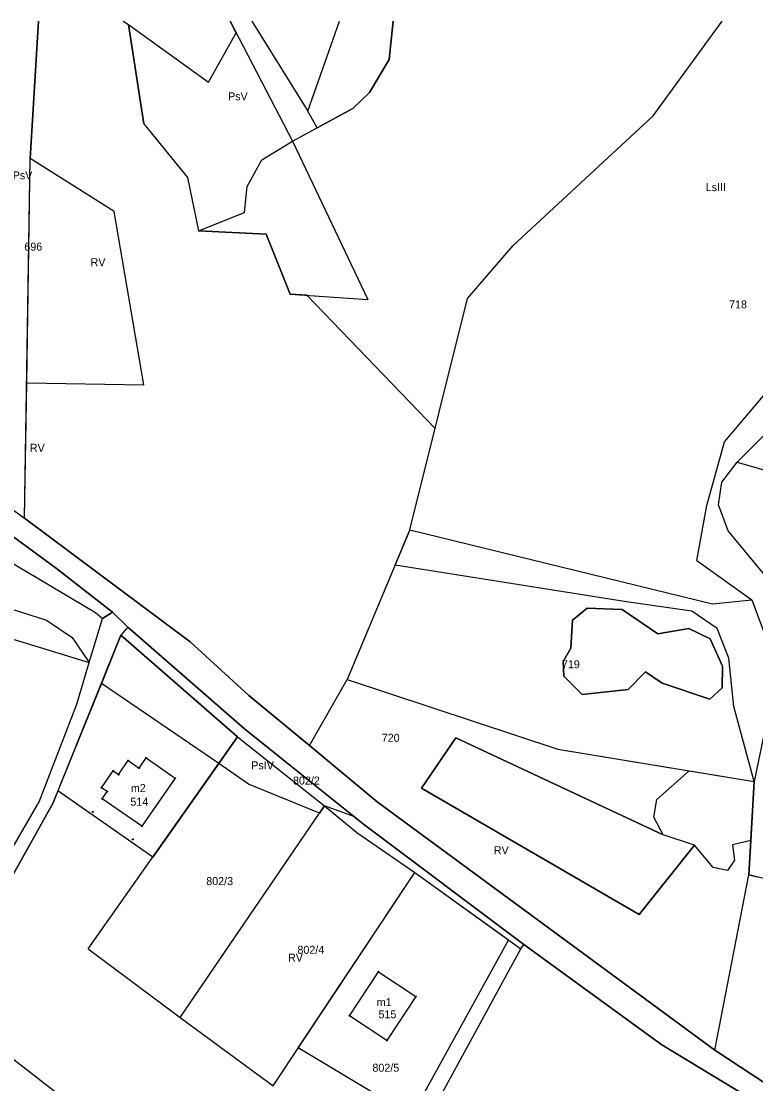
# Model space of a CAD drawing. Extents: x 7498273 to 7499989, y 5499795 to 5500810.
# Drawn here: x 7499690.9 to 7499828.5, y 5500610.4 to 5500809.6 of the extents above; entities that cross this region are included whole.
import ezdxf

# ---------------------------------------------------------------- set-up
doc = ezdxf.new("R2010")
doc.units = 0
for name, color, linetype in [('209-oznaczenie konturu klasyfikacyjnego', 7, 'Continuous'), ('211-numer działki ewidencyjnej', 7, 'Continuous'), ('217-kontur klasyfikacyjny', 7, 'Continuous'), ('218-kontur użytku gruntowego', 7, 'Continuous'), ('219-działka ewidencyjna', 7, 'Continuous'), ('312-budynek ewidencyjny', 7, 'Continuous'), ('312-oznaczenie budynku ewidencyjnego', 7, 'Continuous'), ('312-oznaczenie budynku ewidencyjnego-Atr117', 7, 'Continuous'), ('Punkt budynku', 7, 'Continuous')]:
    doc.layers.add(name, color=color, linetype=linetype)

# ---------------------------------------------------------------- blocks, each defined once
blk = doc.blocks.new('PUNKTBUD')
blk.add_circle((0, 0), 0.09)

msp = doc.modelspace()

# ---------------------------------------------------------------- linework, layer by layer
at = {"layer": '217-kontur klasyfikacyjny'}
for points in [[(7499692.6, 5500783.85), (7499694.121, 5500809.555)], [(7499710.006, 5500809.555), (7499711, 5500808.93)], [(7499731.16, 5500807.4), (7499730.036, 5500809.555)], [(7499734.114, 5500809.555), (7499744.63, 5500792.71)], [(7499744.63, 5500792.71), (7499750.533, 5500809.555)], [(7499760.6, 5500809.555), (7499759.83, 5500802.4)], [(7499711, 5500808.93), (7499725.99, 5500798.12)], [(7499711, 5500808.93), (7499713.85, 5500790.36)], [(7499725.99, 5500798.12), (7499731.16, 5500807.4)], [(7499759.83, 5500802.4), (7499756.17, 5500796.19)], [(7499756.17, 5500796.19), (7499753.05, 5500793.18)], [(7499753.05, 5500793.18), (7499746.33, 5500789.55)], [(7499746.33, 5500789.55), (7499744.63, 5500792.71)], [(7499713.85, 5500790.36), (7499722.07, 5500780.25)], [(7499741.76, 5500787.08), (7499746.33, 5500789.55)], [(7499736, 5500783.58), (7499741.76, 5500787.08)], [(7499691.93, 5500741.79), (7499692.6, 5500783.85)], [(7499708.34, 5500773.87), (7499692.6, 5500783.85)], [(7499733.24, 5500778.61), (7499736, 5500783.58)], [(7499722.07, 5500780.25), (7499724.13, 5500770.26)], [(7499732.76, 5500773.71), (7499733.24, 5500778.61)], [(7499713.89, 5500741.44), (7499708.34, 5500773.87)], [(7499724.13, 5500770.26), (7499732.76, 5500773.71)], [(7499736.78, 5500769.67), (7499724.13, 5500770.26)], [(7499741.31, 5500758.42), (7499736.78, 5500769.67)], [(7499744.4, 5500758.21), (7499741.31, 5500758.42)], [(7499768.47, 5500733.21), (7499744.4, 5500758.21)], [(7499691.53, 5500716.43), (7499691.93, 5500741.79)], [(7499691.93, 5500741.79), (7499713.89, 5500741.44)], [(7499831.76, 5500733.58), (7499825.08, 5500726.95)], [(7499763.74, 5500714.23), (7499768.47, 5500733.21)], [(7499822.18, 5500723.15), (7499825.08, 5500726.95)], [(7499825.08, 5500726.95), (7499880.65, 5500710.94)], [(7499821.56, 5500718.94), (7499822.18, 5500723.15)], [(7499697.51, 5500706.97), (7499681.88, 5500718.4)], [(7499688.31, 5500718.73), (7499691.53, 5500716.43)], [(7499823.35, 5500714.05), (7499821.56, 5500718.94)], [(7499691.53, 5500716.43), (7499722.55, 5500693.26)], [(7499761, 5500707.59), (7499763.74, 5500714.23)], [(7499831.16, 5500704.65), (7499823.35, 5500714.05)], [(7499804.34, 5500700.75), (7499761, 5500707.59)], [(7499708, 5500698.79), (7499697.51, 5500706.97)], [(7499683.07, 5500701.33), (7499695.62, 5500697.33)], [(7499816.55, 5500699.03), (7499804.34, 5500700.75)], [(7499703.63, 5500689.35), (7499706.14, 5500697.61)], [(7499706.14, 5500697.61), (7499708, 5500698.79)], [(7499794.18, 5500697.3), (7499796.97, 5500699.58)], [(7499796.97, 5500699.58), (7499803.48, 5500699.32)], [(7499803.48, 5500699.32), (7499810.16, 5500694.75)], [(7499821.31, 5500695.78), (7499816.55, 5500699.03)], [(7499695.62, 5500697.33), (7499700.45, 5500694.09)], [(7499710.9, 5500695.99), (7499709.58, 5500694.48)], [(7499732.77, 5500676.94), (7499710.9, 5500695.99)], [(7499793.87, 5500692.04), (7499794.18, 5500697.3)], [(7499810.16, 5500694.75), (7499815.98, 5500695.74)], [(7499815.98, 5500695.74), (7499819.99, 5500693.84)], [(7499823.52, 5500690.2), (7499821.31, 5500695.78)], [(7499700.45, 5500694.09), (7499703.63, 5500689.35)], [(7499709.58, 5500694.48), (7499705.92, 5500685.43)], [(7499819.99, 5500693.84), (7499822.28, 5500688.71)], [(7499722.55, 5500693.26), (7499733.56, 5500683.18)], [(7499792.45, 5500689.54), (7499793.87, 5500692.04)], [(7499824.44, 5500681.15), (7499823.52, 5500690.2)], [(7499701.31, 5500681.59), (7499703.63, 5500689.35)], [(7499792.58, 5500686.79), (7499792.45, 5500689.54)], [(7499822.28, 5500688.71), (7499822.22, 5500684.61)], [(7499744.93, 5500673.82), (7499751.95, 5500686.19)], [(7499751.95, 5500686.19), (7499791.46, 5500673.13)], [(7499796.03, 5500683.41), (7499792.58, 5500686.79)], [(7499807.88, 5500687.62), (7499804.62, 5500684.31)], [(7499810.98, 5500685.52), (7499807.88, 5500687.62)], [(7499705.92, 5500685.43), (7499697.79, 5500665.31)], [(7499727.91, 5500670.43), (7499705.92, 5500685.43)], [(7499804.62, 5500684.31), (7499796.03, 5500683.41)], [(7499819.93, 5500682.48), (7499810.98, 5500685.52)], [(7499822.22, 5500684.61), (7499819.93, 5500682.48)], [(7499733.56, 5500683.18), (7499744.93, 5500673.82)], [(7499694.3, 5500663.26), (7499701.31, 5500681.59)], [(7499828.25, 5500667.1), (7499824.44, 5500681.15)], [(7499753.2, 5500660.55), (7499732.77, 5500676.94)], [(7499744.93, 5500673.82), (7499757.58, 5500663.24)], [(7499765.9, 5500665.82), (7499772.34, 5500675.25)], [(7499772.34, 5500675.25), (7499811.21, 5500657.07)], [(7499791.46, 5500673.13), (7499816.06, 5500669.1)], [(7499733.52, 5500666.58), (7499727.91, 5500670.43)], [(7499810.02, 5500663.71), (7499816.06, 5500669.1)], [(7499816.06, 5500669.1), (7499828.25, 5500667.1)], [(7499746.78, 5500661.13), (7499733.52, 5500666.58)], [(7499806.72, 5500642.18), (7499765.9, 5500665.82)], [(7499828.25, 5500667.1), (7499827.59, 5500656)], [(7499697.79, 5500665.31), (7499696.89, 5500663.08)], [(7499681.96, 5500642.08), (7499694.3, 5500663.26)], [(7499696.89, 5500663.08), (7499684.81, 5500641.58)], [(7499747.73, 5500662.52), (7499746.78, 5500661.13)], [(7499753.2, 5500660.55), (7499747.73, 5500662.52)], [(7499757.58, 5500663.24), (7499820.89, 5500616.74)], [(7499809.45, 5500660.39), (7499810.02, 5500663.71)], [(7499755.04, 5500659.07), (7499753.2, 5500660.55)], [(7499811.21, 5500657.07), (7499809.45, 5500660.39)], [(7499785.09, 5500636.56), (7499755.04, 5500659.07)], [(7499827.59, 5500656), (7499824.15, 5500655.21)], [(7499827.59, 5500656), (7499827.21, 5500649.6)], [(7499817.08, 5500655.13), (7499806.72, 5500642.18)], [(7499820.53, 5500650.95), (7499817.08, 5500655.13)], [(7499824.15, 5500655.21), (7499824.58, 5500652.32)], [(7499824.58, 5500652.32), (7499823.24, 5500650.38)], [(7499742.82, 5500617.18), (7499764.64, 5500650.03)], [(7499764.64, 5500650.03), (7499782.19, 5500637.42)], [(7499823.24, 5500650.38), (7499820.53, 5500650.95)], [(7499820.89, 5500616.74), (7499827.21, 5500649.6)], [(7499827.21, 5500649.6), (7499828.82, 5500649.2)], [(7499782.19, 5500637.42), (7499764.06, 5500604.45)], [(7499810.94, 5500617.72), (7499785.09, 5500636.56)], [(7499747.57, 5500569.82), (7499677.4, 5500624.27)], [(7499764.06, 5500604.45), (7499742.82, 5500617.18)], [(7499834.34, 5500603.52), (7499810.94, 5500617.72)], [(7499820.89, 5500616.74), (7499830.36, 5500610.47)]]:
    msp.add_lwpolyline(points, dxfattribs=at)
at = {"layer": '218-kontur użytku gruntowego'}
for points in [[(7499692.6, 5500783.85), (7499694.121, 5500809.555)], [(7499710.006, 5500809.555), (7499711, 5500808.93)], [(7499731.16, 5500807.4), (7499730.036, 5500809.555)], [(7499734.114, 5500809.555), (7499744.63, 5500792.71)], [(7499744.63, 5500792.71), (7499750.533, 5500809.555)], [(7499759.83, 5500802.4), (7499760.6, 5500809.555)], [(7499711, 5500808.93), (7499725.99, 5500798.12)], [(7499711, 5500808.93), (7499713.85, 5500790.36)], [(7499725.99, 5500798.12), (7499731.16, 5500807.4)], [(7499756.17, 5500796.19), (7499759.83, 5500802.4)], [(7499753.05, 5500793.18), (7499756.17, 5500796.19)], [(7499746.33, 5500789.55), (7499753.05, 5500793.18)], [(7499746.33, 5500789.55), (7499744.63, 5500792.71)], [(7499713.85, 5500790.36), (7499722.07, 5500780.25)], [(7499741.76, 5500787.08), (7499746.33, 5500789.55)], [(7499736, 5500783.58), (7499741.76, 5500787.08)], [(7499691.93, 5500741.79), (7499692.6, 5500783.85)], [(7499708.34, 5500773.87), (7499692.6, 5500783.85)], [(7499733.24, 5500778.61), (7499736, 5500783.58)], [(7499722.07, 5500780.25), (7499724.13, 5500770.26)], [(7499732.76, 5500773.71), (7499733.24, 5500778.61)], [(7499713.89, 5500741.44), (7499708.34, 5500773.87)], [(7499724.13, 5500770.26), (7499732.76, 5500773.71)], [(7499736.78, 5500769.67), (7499724.13, 5500770.26)], [(7499741.31, 5500758.42), (7499736.78, 5500769.67)], [(7499744.4, 5500758.21), (7499741.31, 5500758.42)], [(7499768.47, 5500733.21), (7499744.4, 5500758.21)], [(7499691.53, 5500716.43), (7499691.93, 5500741.79)], [(7499691.93, 5500741.79), (7499713.89, 5500741.44)], [(7499831.76, 5500733.58), (7499825.08, 5500726.95)], [(7499763.74, 5500714.23), (7499768.47, 5500733.21)], [(7499822.18, 5500723.15), (7499825.08, 5500726.95)], [(7499825.08, 5500726.95), (7499880.65, 5500710.94)], [(7499821.56, 5500718.94), (7499822.18, 5500723.15)], [(7499697.51, 5500706.97), (7499681.88, 5500718.4)], [(7499688.31, 5500718.73), (7499691.53, 5500716.43)], [(7499823.35, 5500714.05), (7499821.56, 5500718.94)], [(7499722.55, 5500693.26), (7499691.53, 5500716.43)], [(7499761, 5500707.59), (7499763.74, 5500714.23)], [(7499831.16, 5500704.65), (7499823.35, 5500714.05)], [(7499804.34, 5500700.75), (7499761, 5500707.59)], [(7499708, 5500698.79), (7499697.51, 5500706.97)], [(7499683.07, 5500701.33), (7499695.62, 5500697.33)], [(7499816.55, 5500699.03), (7499804.34, 5500700.75)], [(7499703.63, 5500689.35), (7499706.14, 5500697.61)], [(7499706.14, 5500697.61), (7499708, 5500698.79)], [(7499796.97, 5500699.58), (7499794.18, 5500697.3)], [(7499803.48, 5500699.32), (7499796.97, 5500699.58)], [(7499810.16, 5500694.75), (7499803.48, 5500699.32)], [(7499821.31, 5500695.78), (7499816.55, 5500699.03)], [(7499695.62, 5500697.33), (7499700.45, 5500694.09)], [(7499710.9, 5500695.99), (7499709.58, 5500694.48)], [(7499732.77, 5500676.94), (7499710.9, 5500695.99)], [(7499794.18, 5500697.3), (7499793.87, 5500692.04)], [(7499815.98, 5500695.74), (7499810.16, 5500694.75)], [(7499819.99, 5500693.84), (7499815.98, 5500695.74)], [(7499823.52, 5500690.2), (7499821.31, 5500695.78)], [(7499700.45, 5500694.09), (7499703.63, 5500689.35)], [(7499709.58, 5500694.48), (7499705.92, 5500685.43)], [(7499709.58, 5500694.48), (7499731.44, 5500675.44)], [(7499822.28, 5500688.71), (7499819.99, 5500693.84)], [(7499733.56, 5500683.18), (7499722.55, 5500693.26)], [(7499793.87, 5500692.04), (7499792.45, 5500689.54)], [(7499824.44, 5500681.15), (7499823.52, 5500690.2)], [(7499701.31, 5500681.59), (7499703.63, 5500689.35)], [(7499792.45, 5500689.54), (7499792.58, 5500686.79)], [(7499822.22, 5500684.61), (7499822.28, 5500688.71)], [(7499744.93, 5500673.82), (7499751.95, 5500686.19)], [(7499751.95, 5500686.19), (7499791.46, 5500673.13)], [(7499792.58, 5500686.79), (7499796.03, 5500683.41)], [(7499804.62, 5500684.31), (7499807.88, 5500687.62)], [(7499807.88, 5500687.62), (7499810.98, 5500685.52)], [(7499705.92, 5500685.43), (7499697.79, 5500665.31)], [(7499727.91, 5500670.43), (7499705.92, 5500685.43)], [(7499796.03, 5500683.41), (7499804.62, 5500684.31)], [(7499810.98, 5500685.52), (7499819.93, 5500682.48)], [(7499819.93, 5500682.48), (7499822.22, 5500684.61)], [(7499744.93, 5500673.82), (7499733.56, 5500683.18)], [(7499694.3, 5500663.26), (7499701.31, 5500681.59)], [(7499828.25, 5500667.1), (7499824.44, 5500681.15)], [(7499753.2, 5500660.55), (7499732.77, 5500676.94)], [(7499731.44, 5500675.44), (7499727.91, 5500670.43)], [(7499757.58, 5500663.24), (7499744.93, 5500673.82)], [(7499772.34, 5500675.25), (7499765.9, 5500665.82)], [(7499811.21, 5500657.07), (7499772.34, 5500675.25)], [(7499791.46, 5500673.13), (7499816.06, 5500669.1)], [(7499727.91, 5500670.43), (7499715.56, 5500652.9)], [(7499733.52, 5500666.58), (7499727.91, 5500670.43)], [(7499810.02, 5500663.71), (7499816.06, 5500669.1)], [(7499816.06, 5500669.1), (7499828.25, 5500667.1)], [(7499746.78, 5500661.13), (7499733.52, 5500666.58)], [(7499765.9, 5500665.82), (7499806.72, 5500642.18)], [(7499828.25, 5500667.1), (7499827.59, 5500656)], [(7499697.79, 5500665.31), (7499696.89, 5500663.08)], [(7499715.56, 5500652.9), (7499697.79, 5500665.31)], [(7499681.96, 5500642.08), (7499694.3, 5500663.26)], [(7499696.89, 5500663.08), (7499684.81, 5500641.58)], [(7499747.73, 5500662.52), (7499746.78, 5500661.13)], [(7499753.2, 5500660.55), (7499747.73, 5500662.52)], [(7499820.89, 5500616.74), (7499757.58, 5500663.24)], [(7499809.45, 5500660.39), (7499810.02, 5500663.71)], [(7499755.04, 5500659.07), (7499753.2, 5500660.55)], [(7499811.21, 5500657.07), (7499809.45, 5500660.39)], [(7499785.09, 5500636.56), (7499755.04, 5500659.07)], [(7499817.08, 5500655.13), (7499811.21, 5500657.07)], [(7499827.59, 5500656), (7499824.15, 5500655.21)], [(7499827.59, 5500656), (7499827.21, 5500649.6)], [(7499806.72, 5500642.18), (7499817.08, 5500655.13)], [(7499820.53, 5500650.95), (7499817.08, 5500655.13)], [(7499824.15, 5500655.21), (7499824.58, 5500652.32)], [(7499824.58, 5500652.32), (7499823.24, 5500650.38)], [(7499742.82, 5500617.18), (7499764.64, 5500650.03)], [(7499764.64, 5500650.03), (7499782.19, 5500637.42)], [(7499823.24, 5500650.38), (7499820.53, 5500650.95)], [(7499820.89, 5500616.74), (7499827.21, 5500649.6)], [(7499827.21, 5500649.6), (7499828.82, 5500649.2)], [(7499782.19, 5500637.42), (7499764.06, 5500604.45)], [(7499810.94, 5500617.72), (7499785.09, 5500636.56)], [(7499747.57, 5500569.82), (7499677.4, 5500624.27)], [(7499764.06, 5500604.45), (7499742.82, 5500617.18)], [(7499834.34, 5500603.52), (7499810.94, 5500617.72)], [(7499830.36, 5500610.47), (7499820.89, 5500616.74)]]:
    msp.add_lwpolyline(points, dxfattribs=at)
at = {"layer": '219-działka ewidencyjna'}
for points in [[(7499694.121, 5500809.555), (7499692.6, 5500783.85)], [(7499710.006, 5500809.555), (7499711, 5500808.93)], [(7499730.038, 5500809.555), (7499741.76, 5500787.08)], [(7499734.11, 5500809.555), (7499744.63, 5500792.71)], [(7499744.63, 5500792.71), (7499750.533, 5500809.555)], [(7499809.33, 5500791.8), (7499822.264, 5500809.555)], [(7499713.85, 5500790.36), (7499711, 5500808.93)], [(7499809.33, 5500791.8), (7499783.09, 5500767.5)], [(7499713.85, 5500790.36), (7499722.07, 5500780.25)], [(7499741.76, 5500787.08), (7499755.86, 5500757.41)], [(7499691.53, 5500716.43), (7499692.6, 5500783.85)], [(7499722.07, 5500780.25), (7499724.13, 5500770.26)], [(7499724.13, 5500770.26), (7499736.78, 5500769.67)], [(7499736.78, 5500769.67), (7499741.31, 5500758.42)], [(7499774.54, 5500757.62), (7499783.09, 5500767.5)], [(7499741.31, 5500758.42), (7499755.86, 5500757.41)], [(7499763.74, 5500714.23), (7499774.54, 5500757.62)], [(7499822.68, 5500730.74), (7499837.22, 5500747.91)], [(7499819.35, 5500718.78), (7499822.68, 5500730.74)], [(7499681.88, 5500718.4), (7499697.51, 5500706.97)], [(7499688.31, 5500718.73), (7499691.53, 5500716.43)], [(7499817.49, 5500708.48), (7499819.35, 5500718.78)], [(7499722.55, 5500693.26), (7499691.53, 5500716.43)], [(7499763.74, 5500714.23), (7499751.95, 5500686.19)], [(7499763.74, 5500714.23), (7499820.43, 5500700.39)], [(7499639.77, 5500708.54), (7499691.85, 5500693)], [(7499687.91, 5500708.8), (7499704.82, 5500698.78)], [(7499817.49, 5500708.48), (7499827.83, 5500701.11)], [(7499697.51, 5500706.97), (7499708, 5500698.79)], [(7499820.43, 5500700.39), (7499827.83, 5500701.11)], [(7499827.83, 5500701.11), (7499832.62, 5500688.22)], [(7499703.63, 5500689.35), (7499706.14, 5500697.61)], [(7499704.82, 5500698.78), (7499706.14, 5500697.61)], [(7499708, 5500698.79), (7499706.14, 5500697.61)], [(7499708, 5500698.79), (7499710.9, 5500695.99)], [(7499710.9, 5500695.99), (7499709.58, 5500694.48)], [(7499710.9, 5500695.99), (7499732.77, 5500676.94)], [(7499696.89, 5500663.08), (7499709.58, 5500694.48)], [(7499731.44, 5500675.44), (7499709.58, 5500694.48)], [(7499691.85, 5500693), (7499703.63, 5500689.35)], [(7499722.55, 5500693.26), (7499733.56, 5500683.18)], [(7499701.31, 5500681.59), (7499703.63, 5500689.35)], [(7499832.62, 5500688.22), (7499828.25, 5500667.1)], [(7499744.93, 5500673.82), (7499751.95, 5500686.19)], [(7499751.95, 5500686.19), (7499791.46, 5500673.13)], [(7499733.56, 5500683.18), (7499744.93, 5500673.82)], [(7499694.3, 5500663.26), (7499701.31, 5500681.59)], [(7499732.77, 5500676.94), (7499755.04, 5500659.07)], [(7499703.43, 5500635.69), (7499731.44, 5500675.44)], [(7499731.44, 5500675.44), (7499747.73, 5500662.52)], [(7499744.93, 5500673.82), (7499757.58, 5500663.24)], [(7499791.46, 5500673.13), (7499828.25, 5500667.1)], [(7499827.21, 5500649.6), (7499828.25, 5500667.1)], [(7499681.96, 5500642.08), (7499694.3, 5500663.26)], [(7499684.81, 5500641.58), (7499696.89, 5500663.08)], [(7499720.67, 5500622.88), (7499747.73, 5500662.52)], [(7499747.73, 5500662.52), (7499753.79, 5500657.51)], [(7499757.58, 5500663.24), (7499820.89, 5500616.74)], [(7499755.04, 5500659.07), (7499785.09, 5500636.56)], [(7499753.79, 5500657.51), (7499764.64, 5500650.03)], [(7499738.09, 5500610.06), (7499764.64, 5500650.03)], [(7499764.64, 5500650.03), (7499784.51, 5500635.75)], [(7499820.89, 5500616.74), (7499827.21, 5500649.6)], [(7499896.49, 5500632.28), (7499827.21, 5500649.6)], [(7499784.51, 5500635.75), (7499785.09, 5500636.56)], [(7499785.09, 5500636.56), (7499810.94, 5500617.72)], [(7499703.43, 5500635.69), (7499720.67, 5500622.88)], [(7499761.17, 5500592.86), (7499784.51, 5500635.75)], [(7499720.67, 5500622.88), (7499738.09, 5500610.06)], [(7499810.94, 5500617.72), (7499834.34, 5500603.52)], [(7499830.36, 5500610.47), (7499820.89, 5500616.74)]]:
    msp.add_lwpolyline(points, dxfattribs=at)
at = {"layer": '312-budynek ewidencyjny'}
for points in [[(7499709.12, 5500668.36), (7499710.93, 5500670.99)], [(7499710.93, 5500670.99), (7499712.99, 5500669.58)], [(7499712.99, 5500669.58), (7499714.31, 5500671.49)], [(7499714.31, 5500671.49), (7499719.76, 5500667.69)], [(7499705.96, 5500665.91), (7499708.11, 5500669.05)], [(7499708.11, 5500669.05), (7499709.12, 5500668.36)], [(7499706.99, 5500665.2), (7499705.96, 5500665.91)], [(7499719.76, 5500667.69), (7499713.5, 5500658.71)], [(7499706.06, 5500663.85), (7499706.99, 5500665.2)], [(7499713.5, 5500658.71), (7499706.06, 5500663.85)], [(7499752.42, 5500623.19), (7499757.88, 5500631.42)], [(7499757.88, 5500631.42), (7499764.85, 5500626.76)], [(7499764.85, 5500626.76), (7499759.4, 5500618.56)], [(7499759.4, 5500618.56), (7499752.42, 5500623.19)]]:
    msp.add_lwpolyline(points, dxfattribs=at)

# ---------------------------------------------------------------- block references
at = {"layer": 'Punkt budynku'}
for p in [(7499710.93, 5500670.99), (7499714.31, 5500671.49), (7499708.11, 5500669.05), (7499709.12, 5500668.36), (7499712.99, 5500669.58), (7499719.76, 5500667.69), (7499705.96, 5500665.91), (7499706.06, 5500663.85), (7499706.99, 5500665.2), (7499704.35, 5500661.39), (7499713.5, 5500658.71), (7499711.79, 5500656.24), (7499757.88, 5500631.42), (7499764.85, 5500626.76), (7499752.42, 5500623.19), (7499759.4, 5500618.56)]:
    msp.add_blockref('PUNKTBUD', p, dxfattribs=at)

# ---------------------------------------------------------------- texts
at = {"layer": '209-oznaczenie konturu klasyfikacyjnego'}
for s, p in [('PsV', (7499729.67, 5500794.74)), ('PsV', (7499689.31, 5500779.93)), ('LsIII', (7499819.16, 5500777.72)), ('RV', (7499703.91, 5500763.65)), ('RV', (7499692.53, 5500728.86)), ('PsIV', (7499734.01, 5500669.36)), ('RV', (7499779.46, 5500653.45)), ('RV', (7499740.9, 5500633.32))]:
    msp.add_text(s, height=1.5, dxfattribs=at).set_placement(p)
at = {"layer": '211-numer działki ewidencyjnej'}
for s, p in [('696', (7499691.5, 5500766.57)), ('718', (7499823.54, 5500755.74)), ('719', (7499792.22, 5500688.3)), ('720', (7499758.46, 5500674.52)), ('802/2', (7499741.83, 5500666.5)), ('802/3', (7499725.58, 5500647.66)), ('802/4', (7499742.66, 5500634.79)), ('802/5', (7499756.71, 5500612.69))]:
    msp.add_text(s, height=1.5, dxfattribs=at).set_placement(p)
at = {"layer": '312-oznaczenie budynku ewidencyjnego'}
for s, p in [('514', (7499711.36, 5500662.54)), ('515', (7499757.85, 5500622.7))]:
    msp.add_text(s, height=1.5, dxfattribs=at).set_placement(p)
at = {"layer": '312-oznaczenie budynku ewidencyjnego-Atr117'}
for s, p in [('m2', (7499711.446, 5500665.1)), ('m1', (7499757.515, 5500624.99))]:
    msp.add_text(s, height=1.5, dxfattribs=at).set_placement(p)

doc.saveas('drawing.dxf')
